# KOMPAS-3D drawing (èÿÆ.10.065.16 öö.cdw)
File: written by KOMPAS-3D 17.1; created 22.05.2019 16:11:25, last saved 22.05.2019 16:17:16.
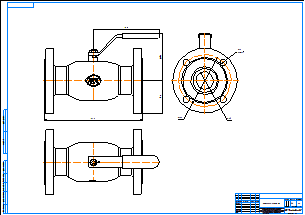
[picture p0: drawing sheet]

Sheet 1: A1, landscape

Title block, sheet 1: name: КШ.10.065.16 Ф/Ф; material: Сталь 20  ГОСТ 1050-2013; mass: 9,6; sheets: 1; sheet format: A1; stored path: \\adlc.lan\data\АДЛ_ПКД\3D-модели\ADL production\Шаровые краны БИВАЛ\КШ_Бивал_серия_10\KOMPAS 2D\КШТ.10.065.16 ФФ.cdw

Views: Спереди 1, Проекционный вид 2, Проекционный вид 3
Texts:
  kka
  adl
  Рама для чертежей
  Лит-Масса-Масштаб
  Материал-Предприятие
  Масштаб
  Изм.
  Лист
  № докум.
  Подп.
  Дата
  Лит.
  Разраб.
  Пров.
  Т.контр.
  Листов
  Внимание! Данный продукт является объектом авторского права ООО «Торговый Дом АДЛ».
  Запрещается изменение, копирование, распространение
  (в том числе путем копирования на другие сайты и ресурсы в Интернете)
  или любое иное использование информации и объектов без предварительного
  согласия правообладателя (ООО «Торговый Дом АДЛ»).
  Н.контр.
  Утв.
  ООО "Торговый дом АДЛ"
  Изменение
  Номер документа
  Подпись
  Обозначение документа
  Наименование изделия
  Масса изделия по ГОСТ 2.109-73
  Порядковый номер листа
  Общее количество листов в документе
  Характер работы, выполненной лицом, подписавшим документ
  Наименование или индекс предприятия, выпускающего документ
  Инв. № подл.
  Подп. и дата
  Взам. инв. №
  Инв. № дубл.
  Инвентарный номер подлинника по ГОСТ 2.501-68
  Подпись принявшего подлинник в отдел технической документации
  Инвентарный номер подлинника, взамен которого выпущен данный подлинник
  Инвентарный номер дубликата по ГОСТ 2.502-68
  Подпись принявшего дубликат в отдел технической документации
  Справ. №
  Перв. примен.
  Обозначение документа, взамен или на основании которого выпущен данный документ
  Обозначение документа, в котором впервые записан данный документ
  Подпись лица, копировавшего чертеж
  Обозначение формата листа
  !Рама для чертежа
Dimensions and other numbers on the sheet: 270; 129,5; 183; 90; 145; 18; 4 отв.; 49; 1:1; 1; 9,6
